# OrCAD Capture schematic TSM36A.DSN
size A; title: TSM36A Surge Protection Device in SOT-23 Package; rev: 1.0; note: Datasheet: SLVSGX7
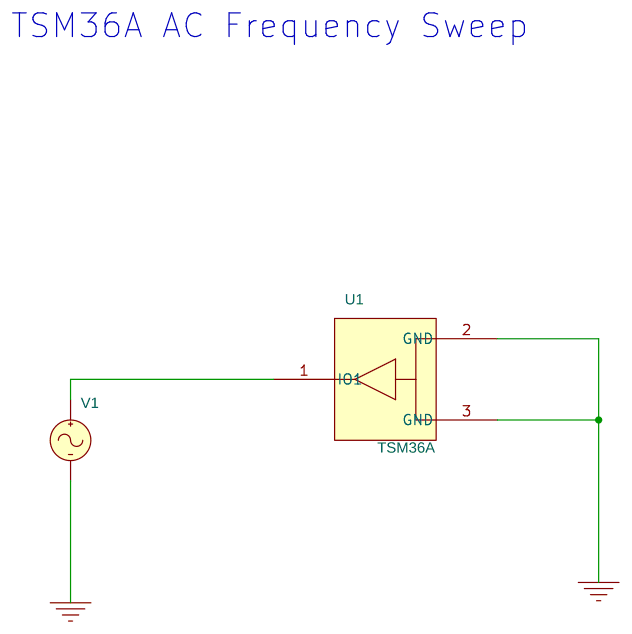
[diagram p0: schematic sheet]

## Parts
U1  TSM36A
V1  VAC

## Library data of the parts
U1 = TSM36A
V1 = VAC

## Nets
0: U1.2(GND) U1.3(GND) V1.2(-)
N02961: U1.1(IO1) V1.1(+)

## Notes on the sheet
- TSM36A AC Frequency Sweep
